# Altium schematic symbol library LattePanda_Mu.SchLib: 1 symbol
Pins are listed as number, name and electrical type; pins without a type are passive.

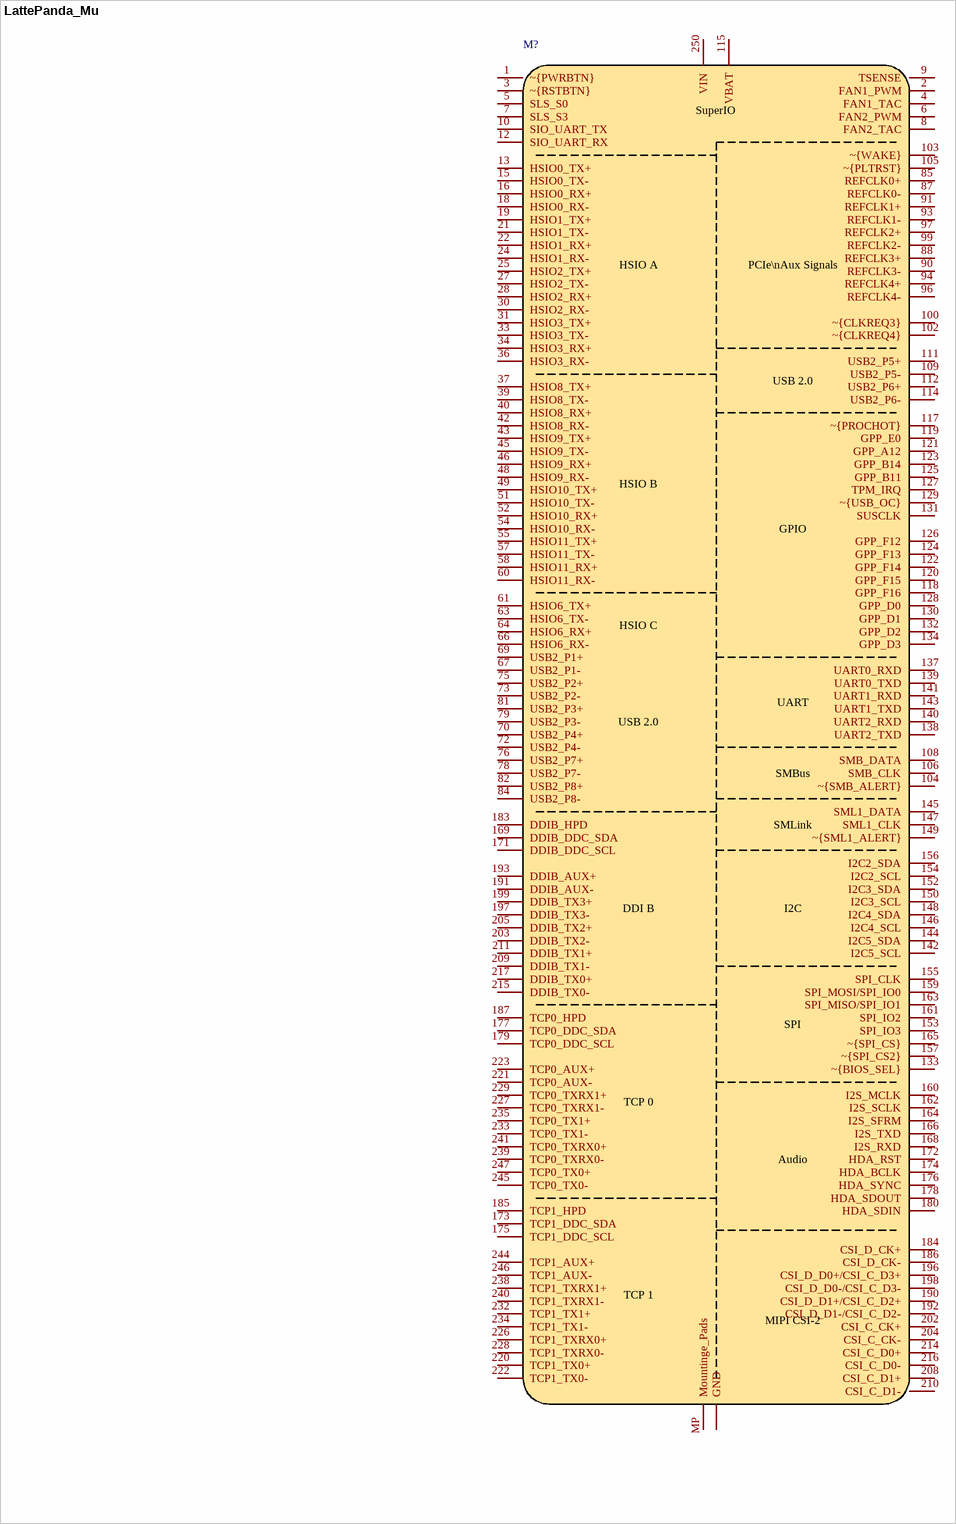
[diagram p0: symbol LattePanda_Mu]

## LattePanda_Mu
designator M?  (value not drawn)
A micro computing module with x86 processer, RAM and eMMC.; ki_keywords: lattepanda mu x86 compute module; ki_fp_filters: *LattePanda*; Add into BOM: yes
footprint Module_LattePanda:LattePanda_Module_H8.0mm_Horizontal
pins: 1 ~{PWRBTN}, 2 FAN1_PWM, 3 ~{RSTBTN}, 4 FAN1_TAC, 5 SLS_S0, 6 FAN2_PWM, 7 SLS_S3, 8 FAN2_TAC, 9 TSENSE, 10 SIO_UART_TX, 11 GND, 12 SIO_UART_RX, 13 HSIO0_TX+, 14 GND, 15 HSIO0_TX-, 16 HSIO0_RX+, 17 GND, 18 HSIO0_RX-, 19 HSIO1_TX+, 20 GND, 21 HSIO1_TX-, 22 HSIO1_RX+, 23 GND, 24 HSIO1_RX-, 25 HSIO2_TX+, 26 GND, 27 HSIO2_TX-, 28 HSIO2_RX+, 29 GND, 30 HSIO2_RX-, 31 HSIO3_TX+, 32 GND, 33 HSIO3_TX-, 34 HSIO3_RX+, 35 GND, 36 HSIO3_RX-, 37 HSIO8_TX+, 38 GND, 39 HSIO8_TX-, 40 HSIO8_RX+, 41 GND, 42 HSIO8_RX-, 43 HSIO9_TX+, 44 GND, 45 HSIO9_TX-, 46 HSIO9_RX+, 47 GND, 48 HSIO9_RX-, 49 HSIO10_TX+, 50 GND, 51 HSIO10_TX-, 52 HSIO10_RX+, 53 GND, 54 HSIO10_RX-, 55 HSIO11_TX+, 56 GND, 57 HSIO11_TX-, 58 HSIO11_RX+, 59 GND, 60 HSIO11_RX-, 61 HSIO6_TX+, 62 GND, 63 HSIO6_TX-, 64 HSIO6_RX+, 65 GND, 66 HSIO6_RX-, 67 USB2_P1-, 68 GND, 69 USB2_P1+, 70 USB2_P4+, 71 GND, 72 USB2_P4-, 73 USB2_P2-, 74 GND, 75 USB2_P2+, 76 USB2_P7+, 77 GND, 78 USB2_P7-, 79 USB2_P3-, 80 GND, 81 USB2_P3+, 82 USB2_P8+, 83 GND, 84 USB2_P8-, 85 REFCLK0+, 86 GND, 87 REFCLK0-, 88 REFCLK3+, 89 GND, 90 REFCLK3-, 91 REFCLK1+, 92 GND, 93 REFCLK1-, 94 REFCLK4+, 95 GND, 96 REFCLK4-, 97 REFCLK2+, 98 GND, 99 REFCLK2-, 100 ~{CLKREQ3}, 101 GND, 102 ~{CLKREQ4}, 103 ~{WAKE}, 104 ~{SMB_ALERT}, 105 ~{PLTRST}, 106 SMB_CLK, 107 GND, 108 SMB_DATA, 109 USB2_P5-, 110 GND, 111 USB2_P5+, 112 USB2_P6+, 113 GND, 114 USB2_P6-, 115 VBAT, 116 GND, 117 ~{PROCHOT}, 118 GPP_F16, 119 GPP_E0, 120 GPP_F15, 121 GPP_A12, 122 GPP_F14, 123 GPP_B14, 124 GPP_F13, 125 GPP_B11, 126 GPP_F12, 127 TPM_IRQ, 128 GPP_D0, 129 ~{USB_OC}, 130 GPP_D1, 131 SUSCLK, 132 GPP_D2, 133 ~{BIOS_SEL}, 134 GPP_D3, 135 GND, 136 GND, 137 UART0_RXD, 138 UART2_TXD, 139 UART0_TXD, 140 UART2_RXD, 141 UART1_RXD, 142 I2C5_SCL, 143 UART1_TXD, 144 I2C5_SDA, 145 SML1_DATA, 146 I2C4_SCL, 147 SML1_CLK, 148 I2C4_SDA, 149 ~{SML1_ALERT}, 150 I2C3_SCL, 151 GND, 152 I2C3_SDA, 153 SPI_IO3, 154 I2C2_SCL, 155 SPI_CLK, 156 I2C2_SDA, 157 ~{SPI_CS2}, 158 GND, 159 SPI_MOSI/SPI_IO0, 160 I2S_MCLK, 161 SPI_IO2, 162 I2S_SCLK, 163 SPI_MISO/SPI_IO1, 164 I2S_SFRM, 165 ~{SPI_CS}, 166 I2S_TXD, 167 GND, 168 I2S_RXD, 169 DDIB_DDC_SDA, 170 GND, 171 DDIB_DDC_SCL, 172 HDA_RST, 173 TCP1_DDC_SDA, 174 HDA_BCLK, 175 TCP1_DDC_SCL, 176 HDA_SYNC, 177 TCP0_DDC_SDA, 178 HDA_SDOUT, 179 TCP0_DDC_SCL, 180 HDA_SDIN, 181 GND, 182 GND, 183 DDIB_HPD, 184 CSI_D_CK+, 185 TCP1_HPD, 186 CSI_D_CK-, 187 TCP0_HPD, 188 GND, 189 GND, 190 CSI_D_D1+/CSI_C_D2+, 191 DDIB_AUX-, 192 CSI_D_D1-/CSI_C_D2-, 193 DDIB_AUX+, 194 GND, 195 GND, 196 CSI_D_D0+/CSI_C_D3+, 197 DDIB_TX3-, 198 CSI_D_D0-/CSI_C_D3-, 199 DDIB_TX3+, 200 GND, 201 GND, 202 CSI_C_CK+, 203 DDIB_TX2-, 204 CSI_C_CK-, 205 DDIB_TX2+, 206 GND, 207 GND, 208 CSI_C_D1+, 209 DDIB_TX1-, 210 CSI_C_D1-, 211 DDIB_TX1+, 212 GND, 213 GND, 214 CSI_C_D0+, 215 DDIB_TX0-, 216 CSI_C_D0-, 217 DDIB_TX0+, 218 GND, 219 GND, 220 TCP1_TX0+, 221 TCP0_AUX-, 222 TCP1_TX0-, 223 TCP0_AUX+, 224 GND, 225 GND, 226 TCP1_TXRX0+, 227 TCP0_TXRX1-, 228 TCP1_TXRX0-, 229 TCP0_TXRX1+, 230 GND, 231 GND, 232 TCP1_TX1+, 233 TCP0_TX1-, 234 TCP1_TX1-, 235 TCP0_TX1+, 236 GND, 237 GND, 238 TCP1_TXRX1+, 239 TCP0_TXRX0-, 240 TCP1_TXRX1-, 241 TCP0_TXRX0+, 242 GND, 243 GND, 244 TCP1_AUX+, 245 TCP0_TX0-, 246 TCP1_AUX-, 247 TCP0_TX0+, 248 GND, 249 GND, 250 VIN, 251 VIN, 252 VIN, 253 VIN, 254 VIN, 255 VIN, 256 VIN, 257 VIN, 258 VIN, 259 VIN, 260 VIN, MP Mountinge_Pads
